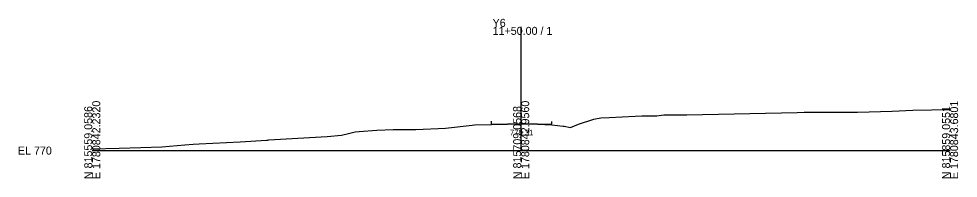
# Model space of a CAD drawing. Extents: x -26 to 1603, y -10 to 6024.
# Drawn here: x -25.7 to 302.8, y 1490.3 to 1546.2 of the extents above; entities that cross this region are included whole.
import ezdxf

# ---------------------------------------------------------------- set-up
doc = ezdxf.new("R2010")
doc.units = 0
for name, color, linetype in [('Exist Cross Section Cell', 7, 'Continuous'), ('Exist XS Center Line Elevation Label', 7, 'Continuous'), ('Exist XS Ground Line', 7, 'Continuous'), ('Prop XS EOT Tick Mark', 7, 'Continuous'), ('Prop XS Finish Grade Pavement', 7, 'Continuous')]:
    doc.layers.add(name, color=color, linetype=linetype)

msp = doc.modelspace()

# ---------------------------------------------------------------- linework, layer by layer
at = {"layer": 'Exist Cross Section Cell'}
for p, q in [((150, 1500), (150, 1543.35)), ((0, 1500), (150, 1500)), ((150, 1500), (300, 1500))]:
    msp.add_line(p, q, dxfattribs=at)
at = {"layer": 'Exist XS Ground Line'}
for p, q in [((175.43, 1511.05), (177.82, 1511.46)), ((177.82, 1511.46), (180.81, 1511.59)), ((180.81, 1511.59), (189.83, 1512.09)), ((189.83, 1512.09), (192.21, 1512.15)), ((192.21, 1512.15), (197.5, 1512.16)), ((197.5, 1512.16), (199.91, 1512.47)), ((199.91, 1512.47), (207.91, 1512.52)), ((207.91, 1512.52), (246.49, 1513.36)), ((246.49, 1513.36), (249.01, 1513.42)), ((249.01, 1513.42), (249.4, 1513.42)), ((249.4, 1513.42), (255.72, 1513.46)), ((255.72, 1513.46), (267.63, 1513.49)), ((267.63, 1513.49), (279.7, 1513.85)), ((279.7, 1513.85), (286.94, 1514.13)), ((286.94, 1514.13), (300, 1514.45)), ((123.52, 1507.86), (132.89, 1508.92)), ((132.89, 1508.92), (133.67, 1509)), ((133.67, 1509), (139.68, 1509.13)), ((139.68, 1509.13), (145.23, 1509.26)), ((145.23, 1509.26), (150.14, 1509.32)), ((150.14, 1509.32), (155.66, 1509.2)), ((155.66, 1509.2), (160.78, 1509.07)), ((160.78, 1509.07), (164.72, 1508.54)), ((164.72, 1508.54), (165.09, 1508.5)), ((165.09, 1508.5), (167.2, 1508.1)), ((167.2, 1508.1), (170.08, 1509.29)), ((170.08, 1509.29), (175.43, 1511.05)), ((61.75, 1503.71), (80.02, 1504.78)), ((80.02, 1504.78), (82.15, 1504.99)), ((82.15, 1504.99), (87.19, 1505.42)), ((87.19, 1505.42), (89.67, 1505.95)), ((89.67, 1505.95), (91.96, 1506.58)), ((91.96, 1506.58), (93.34, 1506.73)), ((93.34, 1506.73), (99.55, 1507.13)), ((99.55, 1507.13), (105.24, 1507.41)), ((105.24, 1507.41), (113.13, 1507.43)), ((113.13, 1507.43), (123.52, 1507.86)), ((24.28, 1501.35), (32.4, 1502.04)), ((32.4, 1502.04), (35.26, 1502.24)), ((35.26, 1502.24), (37.38, 1502.35)), ((37.38, 1502.35), (51.75, 1503.03)), ((51.75, 1503.03), (60.91, 1503.65)), ((60.91, 1503.65), (61.37, 1503.68)), ((61.37, 1503.68), (61.75, 1503.71)), ((0, 1500.58), (9.44, 1500.83)), ((9.44, 1500.83), (16.95, 1501.05)), ((16.95, 1501.05), (24.28, 1501.35))]:
    msp.add_line(p, q, dxfattribs=at)
at = {"layer": 'Prop XS EOT Tick Mark'}
for p, q in [((139.67, 1509.26), (139.67, 1510.26)), ((160.78, 1509.2), (160.78, 1510.2))]:
    msp.add_line(p, q, dxfattribs=at)
at = {"layer": 'Prop XS Finish Grade Pavement'}
for p, q in [((139.67, 1509.26), (145.23, 1509.39)), ((145.23, 1509.39), (150.14, 1509.44)), ((150.14, 1509.44), (155.66, 1509.32)), ((155.66, 1509.32), (160.78, 1509.2))]:
    msp.add_line(p, q, dxfattribs=at)

# ---------------------------------------------------------------- texts
at = {"layer": 'Exist Cross Section Cell'}
for s, p in [('Y6', (140, 1543.35)), ('11+50.00 / 1', (140, 1540.55)), ('EL 770', (-26, 1498.6))]:
    msp.add_text(s, height=2.8, dxfattribs=at).set_placement(p)
for s, p in [('N 815559.0586', (0, 1490)), ('E 1780842.2320', (2.8, 1490)), ('N 815709.0568', (150, 1490)), ('E 1780842.9560', (152.8, 1490)), ('N 815859.0551', (300, 1490)), ('E 1780843.6801', (302.8, 1490))]:
    msp.add_text(s, height=2.8, rotation=90, dxfattribs=at).set_placement(p)
at = {"layer": 'Exist XS Center Line Elevation Label'}
msp.add_text('779.31', height=2, dxfattribs=at).set_placement((146.08, 1505.31))

doc.saveas('drawing.dxf')
